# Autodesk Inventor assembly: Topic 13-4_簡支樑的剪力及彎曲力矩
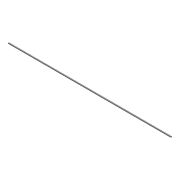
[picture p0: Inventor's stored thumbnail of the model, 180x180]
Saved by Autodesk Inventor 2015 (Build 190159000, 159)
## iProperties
Created: 2020-03
Part Number: Topic 13-4_簡支樑的剪力及彎曲力矩
Document SubType Name: Assembly
Designer: 徐冠倫
Mass: 12110.5 g
Surface Area: 10291.1 cm^2
Volume: 1542.74 cm^3
Density: 7.85 g/cm^3
_SolveAssemblyDoc: Frame Generator Solve Assembly
_Version: 15.0.0
Author: 徐冠倫
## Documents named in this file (3)
- C:\Users\徐冠倫\Desktop\Topic 13-4_簡支樑的剪力及彎曲力矩\Topic 13-4_簡支樑的剪力及彎曲力矩.iam
- C:\Users\徐冠倫\Desktop\Topic 13-4_簡支樑的剪力及彎曲力矩\Topic 13-4_簡支樑的剪力及彎曲力矩.ipt
- C:\Users\徐冠倫\Desktop\Topic 13-4_簡支樑的剪力及彎曲力矩\Topic 13-4_簡支樑的剪力及彎曲力矩\Frame\Frame0001.iam
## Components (2 placed, 2 different names)
1. Topic 13-4_簡支樑的剪力及彎曲力矩:1
2. Frame0001:1 [sub-assembly]
